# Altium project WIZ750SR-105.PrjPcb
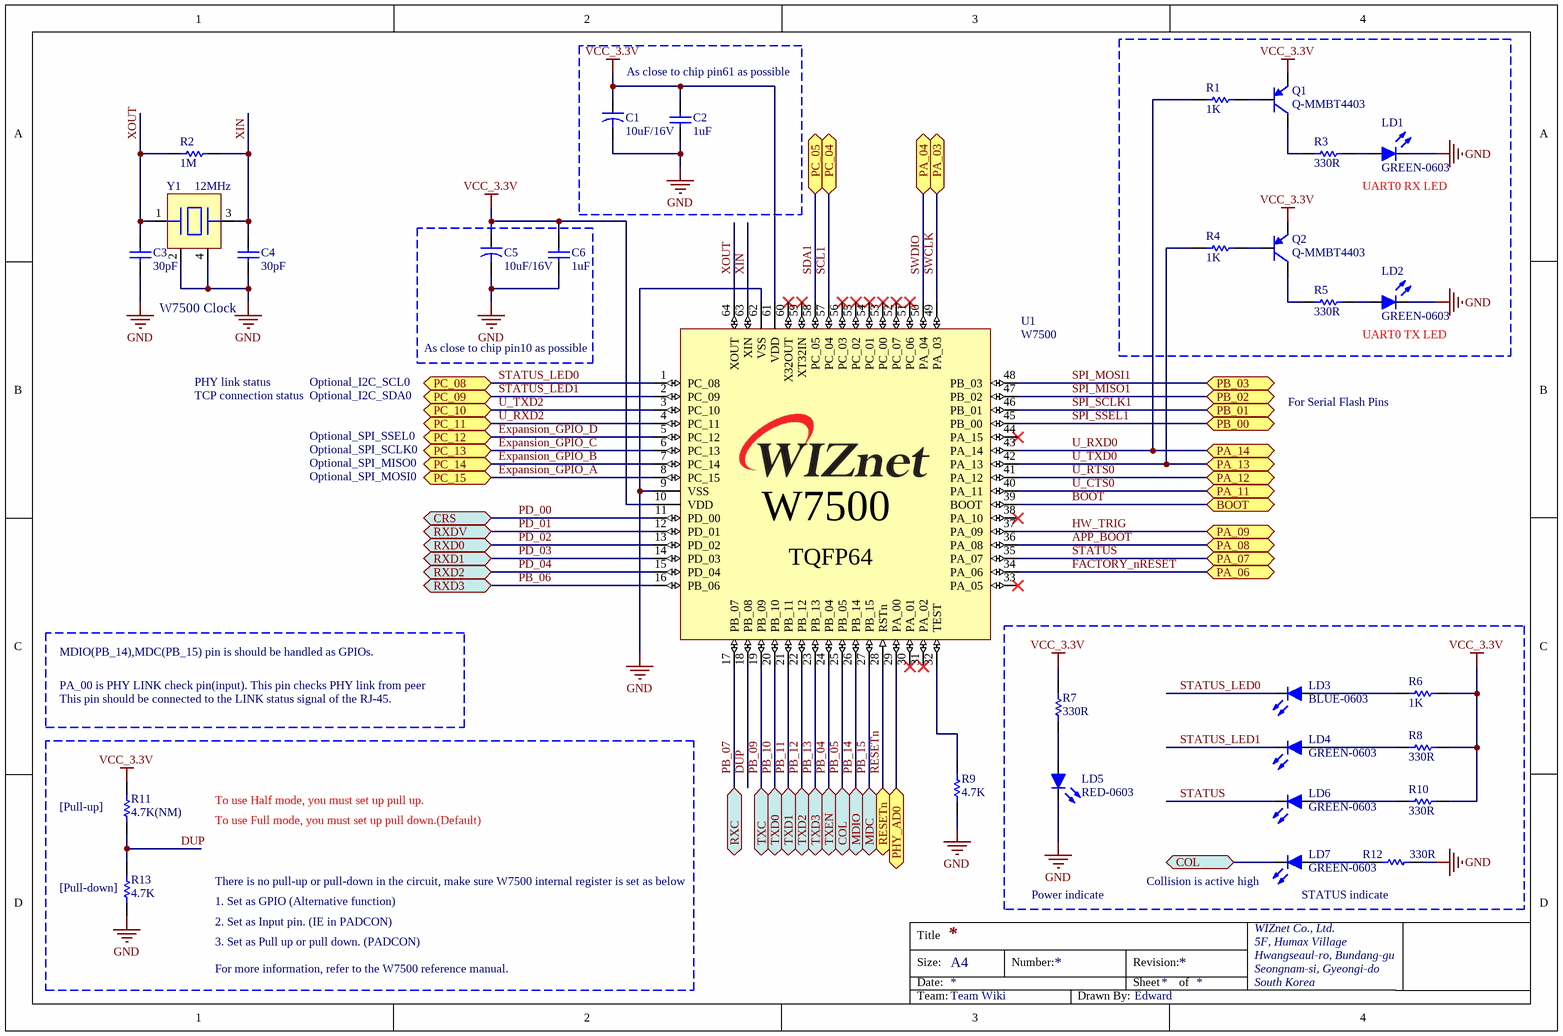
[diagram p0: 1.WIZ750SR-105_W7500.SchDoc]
4 sheets, 82 parts. Net scope: flat (ports and power ports of the same name join across sheets).
Board file: WIZ750SR-105.PcbDoc
Sheets:
  1.WIZ750SR-105_W7500.SchDoc
  2.WIZ750SR-105_IP101GRI.SchDoc
  3.WIZ750SR-105_OPTIONAL.SchDoc
  4.WIZ750SR-105_PINOUT.SchDoc

## Sheet 1.WIZ750SR-105_W7500.SchDoc
size A4; Team: Wiki

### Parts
C1  10uF/16V  [CAP-A Size]
C2  1uF  [CAP-0603]
C3  30pF  [CAP-0603]
C4  30pF  [CAP-0603]
C5  10uF/16V  [CAP-A Size]
C6  1uF  [CAP-0603]
LD1  GREEN-0603  [LED-0603-GREEN]
LD2  GREEN-0603  [LED-0603-GREEN]
LD3  BLUE-0603  [LED-0603-BLUE]
LD4  GREEN-0603  [LED-0603-GREEN]
LD5  RED-0603  [LED-0603-RED]
LD6  GREEN-0603  [LED-0603-GREEN]
LD7  GREEN-0603  [LED-0603-GREEN]
Q1  Q-MMBT4403  [SOT-23-3L]
Q2  Q-MMBT4403  [SOT-23-3L]
R1  1K  [RES-0603]
R2  1M  [RES-0603]
R3  330R  [RES-0603]
R4  1K  [RES-0603]
R5  330R  [RES-0603]
R6  1K  [RES-0603]
R7  330R  [RES-0603]
R8  330R  [RES-0603]
R9  4.7K  [RES-0603]
R10  330R  [RES-0603]
R11  4.7K(NM)  [RES-0603]
R12  330R  [RES-0603]
R13  4.7K  [RES-0603]
U1  W7500  [W7500-LQFP64]
Y1  12MHz  [OSC-TZ1067B]

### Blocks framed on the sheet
As close to chip pin61 as possible: C1 C2
As close to chip pin10 as possible: C5 C6

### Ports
BOOT, COL, CRS, MDC, MDIO, PA_03, PA_04, PA_06, PA_07, PA_08, PA_09, PA_11, PA_12, PA_13, PA_14, PB_00, PB_01, PB_02, PB_03, PC_04, PC_05, PC_08, PC_09, PC_10, PC_11, PC_12, PC_13, PC_14, PC_15, PHY_AD0, RESETn, RXC, RXD0, RXD1, RXD2, RXD3, RXDV, TXC, TXD0, TXD1, TXD2, TXD3, TXEN

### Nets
GND: C1.2 C2.1 C3.1 C4.1 C5.2 C6.1 LD1.2(K) LD2.2(K) LD5.2(K) R9.1 R12.2 R13.1 U1.9(VSS) U1.62(VSS) Y1.2 Y1.4
VCC_3.3V: C1.1 C2.2 C5.1 C6.2 Q1.2(E) Q2.2(E) R6.2 R7.1 R8.2 R10.2 R11.2 U1.10(VDD) U1.61(VDD)
APP_BOOT: U1.36(PA_08) ; port PA_08
BOOT: U1.39(BOOT) ; port BOOT
DUP: R11.1 R13.2 U1.18(PB_08)
Expansion_GPIO_A: U1.8(PC_15) ; port PC_15
Expansion_GPIO_B: U1.7(PC_14) ; port PC_14
Expansion_GPIO_C: U1.6(PC_13) ; port PC_13
Expansion_GPIO_D: U1.5(PC_12) ; port PC_12
FACTORY_nRESET: U1.34(PA_06) ; port PA_06
HW_TRIG: U1.37(PA_09) ; port PA_09
PB_04: U1.24(PB_04) ; port TXEN
PB_05: LD7.2(K) U1.25(PB_05) ; port COL
PB_06: U1.16(PB_06) ; port RXD3
PB_07: U1.17(PB_07) ; port RXC
PB_09: U1.19(PB_09) ; port TXC
PB_10: U1.20(PB_10) ; port TXD0
PB_11: U1.21(PB_11) ; port TXD1
PB_12: U1.22(PB_12) ; port TXD2
PB_13: U1.23(PB_13) ; port TXD3
PB_14: U1.26(PB_14) ; port MDIO
PB_15: U1.27(PB_15) ; port MDC
PD_00: U1.11(PD_00) ; port CRS
PD_01: U1.12(PD_01) ; port RXDV
PD_02: U1.13(PD_02) ; port RXD0
PD_03: U1.14(PD_03) ; port RXD1
PD_04: U1.15(PD_04) ; port RXD2
PHY_AD0: U1.29(PA_00) ; port PHY_AD0
RESETn: U1.28(RSTn) ; port RESETn
SCL1: U1.57(PC_04) ; port PC_04
SDA1: U1.58(PC_05) ; port PC_05
SPI_MISO1: U1.47(PB_02) ; port PB_02
SPI_MOSI1: U1.48(PB_03) ; port PB_03
SPI_SCLK1: U1.46(PB_01) ; port PB_01
SPI_SSEL1: U1.45(PB_00) ; port PB_00
STATUS: LD6.2(K) U1.35(PA_07) ; port PA_07
STATUS_LED0: LD3.2(K) U1.1(PC_08) ; port PC_08
STATUS_LED1: LD4.2(K) U1.2(PC_09) ; port PC_09
SWCLK: U1.49(PA_03) ; port PA_03
SWDIO: U1.50(PA_04) ; port PA_04
U_CTS0: U1.40(PA_11) ; port PA_11
U_RTS0: U1.41(PA_12) ; port PA_12
U_RXD0: R1.2 U1.43(PA_14) ; port PA_14
U_RXD2: U1.4(PC_11) ; port PC_11
U_TXD0: R4.2 U1.42(PA_13) ; port PA_13
U_TXD2: U1.3(PC_10) ; port PC_10
XIN: C4.2 R2.2 U1.63(XIN) Y1.3
XOUT: C3.2 R2.1 U1.64(XOUT) Y1.1
NetLD1_1: LD1.1(A) R3.1
NetLD2_1: LD2.1(A) R5.2
NetLD3_1: LD3.1(A) R6.1
NetLD4_1: LD4.1(A) R8.1
NetLD5_1: LD5.1(A) R7.2
NetLD6_1: LD6.1(A) R10.1
NetLD7_1: LD7.1(A) R12.1
NetQ1_1: Q1.1(B) R1.1
NetQ1_3: Q1.3(C) R3.2
NetQ2_1: Q2.1(B) R4.1
NetQ2_3: Q2.3(C) R5.1
NetR9_2: R9.2 U1.32(TEST)

Not connected (* = marked no-connect by the designer): U1 30(PA_01)* 31(PA_02)* 33(PA_05)* 38(PA_10)* 44(PA_15)* 51(PC_06)* 52(PC_07)* 53(PC_00)* 54(PC_01)* 55(PC_02)* 56(PC_03)* 59(XT32IN)* 60(X32OUT)*

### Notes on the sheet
- UART0 RX LED
- W7500 Clock
- PHY link status
- Optional_I2C_SCL0
- UART0 TX LED
- TCP connection status
- Optional_I2C_SDA0
- Optional_SPI_SSEL0
- For Serial Flash Pins
- Optional_SPI_SCLK0
- Optional_SPI_MISO0
- Optional_SPI_MOSI0
- MDIO(PB_14),MDC(PB_15) pin is should be handled as GPIOs.
- PA_00 is PHY LINK check pin(input). This pin checks PHY link from peer
- This pin should be connected to the LINK status signal of the RJ-45.
- (near R11) [Pull-up]
- To use Half mode, you must set up pull up.
- To use Full mode, you must set up pull down.(Default)
- (near R13) [Pull-down]
- There is no pull-up or pull-down in the circuit, make sure W7500 internal register is set as below
- 1. Set as GPIO (Alternative function)
- 2. Set as Input pin. (IE in PADCON)
- Power indicate
- (near LD7) Collision is active high
- STATUS indicate
- 3. Set as Pull up or pull down. (PADCON)
- For more information, refer to the W7500 reference manual.

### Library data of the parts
C1 C5 = CAP-A Size: Tantla CAP A Size EIA/IECQ 3216
C2-C4 C6 = CAP-0603: Ceramic CAP 0603(1608)
LD1-LD7 = LED-0603
Q1 Q2 = Q-MMBT4403: PNP General-Purpose Amplifier
R1-R13 = RES-0603
U1 = W7500: WIZnet ARM Cortex-M0
Y1 = OSC-TZ1067B-12MHz: X-tal 12MHz,3.2x2.5 SMD, CL=20pF

## Sheet 2.WIZ750SR-105_IP101GRI.SchDoc
size A4; Team: Wiki
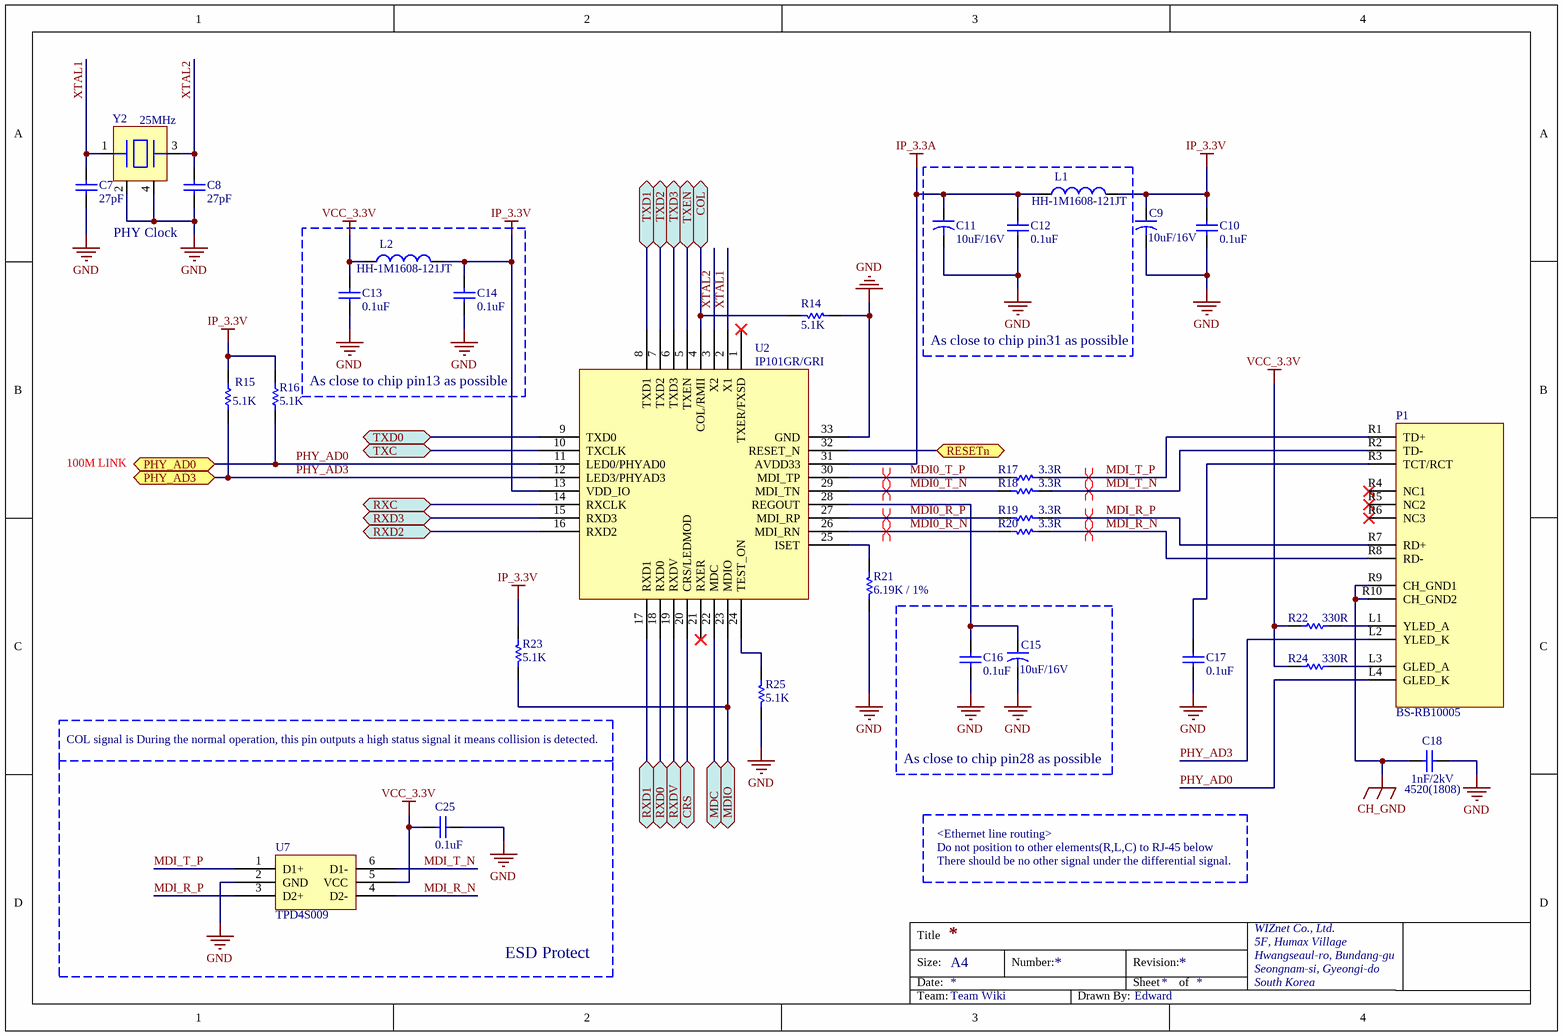
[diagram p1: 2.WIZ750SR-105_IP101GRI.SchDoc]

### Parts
C7  27pF  [CAP-0603]
C8  27pF  [CAP-0603]
C9  10uF/16V  [CAP-A Size]
C10  0.1uF  [CAP-0603]
C11  10uF/16V  [CAP-A Size]
C12  0.1uF  [CAP-0603]
C13  0.1uF  [CAP-0603]
C14  0.1uF  [CAP-0603]
C15  10uF/16V  [CAP-A Size]
C16  0.1uF  [CAP-0603]
C17  0.1uF  [CAP-0603]
C18  1nF/2kV  [CAP-1808]
C25  0.1uF  [CAP-0603]
L1  HH-1M1608-121JT  [IND-0603]
L2  HH-1M1608-121JT  [IND-0603]
P1  BS-RB10005  [RJ45-RB10005]
R14  5.1K  [RES-0603]
R15  5.1K  [RES-0603]
R16  5.1K  [RES-0603]
R17  3.3R  [RES-0603]
R18  3.3R  [RES-0603]
R19  3.3R  [RES-0603]
R20  3.3R  [RES-0603]
R21  6.19K / 1%  [RES-0603]
R22  330R  [RES-0603]
R23  5.1K  [RES-0603]
R24  330R  [RES-0603]
R25  5.1K  [RES-0603]
U2  IP101GR/GRI  [QFN32(0.4/4X4)]
U7  TPD4S009  [SOT-23-6L]
Y2  25MHz  [OSC-82J0626]

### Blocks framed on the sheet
As close to chip pin31 as possible: C11 C12 L1
As close to chip pin13 as possible: C13 C14 L2
As close to chip pin28 as possible: C15 C16

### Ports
COL, CRS, MDC, MDIO, PHY_AD0, PHY_AD3, RESETn, RXC, RXD0, RXD1, RXD2, RXD3, RXDV, TXC, TXD0, TXD1, TXD2, TXD3, TXEN

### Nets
CH_GND: C18.2 P1.R9(CH_GND1) P1.R10(CH_GND2)
GND: C7.1 C8.1 C9.2 C10.1 C11.2 C12.1 C13.1 C14.2 C15.2 C16.1 C17.1 C18.1 C25.2 R14.1 R21.1 R25.1 U2.33(GND) U7.2(GND) Y2.2 Y2.4
IP_3.3A: C11.1 C12.2 L1.1 U2.31(AVDD33)
IP_3.3V: C9.1 C10.2 C14.1 L1.2 L2.2 R15.1 R16.1 R23.2 U2.13(VDD_IO)
VCC_3.3V: C13.2 C25.1 L2.1 R22.1 R24.1 U7.5(VCC)
MDI0_R_N: R20.2 U2.26(MDI_RN)
MDI0_R_P: R19.2 U2.27(MDI_RP)
MDI0_T_N: R18.2 U2.29(MDI_TN)
MDI0_T_P: R17.2 U2.30(MDI_TP)
MDI_R_N: P1.R8(RD-) R20.1 U7.4(D2-)
MDI_R_P: P1.R7(RD+) R19.1 U7.3(D2+)
MDI_T_N: P1.R2(TD-) R18.1 U7.6(D1-)
MDI_T_P: P1.R1(TD+) R17.1 U7.1(D1+)
PB_04: U2.5(TXEN) ; port TXEN
PB_05: R14.2 U2.4(COL/RMII) ; port COL
PB_06: U2.15(RXD3) ; port RXD3
PB_07: U2.14(RXCLK) ; port RXC
PB_09: U2.10(TXCLK) ; port TXC
PB_10: U2.9(TXD0) ; port TXD0
PB_11: U2.8(TXD1) ; port TXD1
PB_12: U2.7(TXD2) ; port TXD2
PB_13: U2.6(TXD3) ; port TXD3
PB_14: R23.1 U2.23(MDIO) ; port MDIO
PB_15: U2.22(MDC) ; port MDC
PD_00: U2.20(CRS/LEDMOD) ; port CRS
PD_01: U2.19(RXDV) ; port RXDV
PD_02: U2.18(RXD0) ; port RXD0
PD_03: U2.17(RXD1) ; port RXD1
PD_04: U2.16(RXD2) ; port RXD2
PHY_AD0: P1.L4(GLED_K) R16.2 U2.11(LED0/PHYAD0) ; port PHY_AD0
PHY_AD3: P1.L2(YLED_K) R15.2 U2.12(LED3/PHYAD3) ; port PHY_AD3
RESETn: U2.32(RESET_N) ; port RESETn
XTAL1: C7.2 U2.2(X1) Y2.1
XTAL2: C8.2 U2.3(X2) Y2.3
NetC15_1: C15.1 C16.2 U2.28(REGOUT)
NetC17_2: C17.2 P1.R3(TCT/RCT)
NetP1_L1: P1.L1(YLED_A) R22.2
NetP1_L3: P1.L3(GLED_A) R24.2
NetR21_2: R21.2 U2.25(ISET)
NetR25_2: R25.2 U2.24(TEST_ON)

Not connected (* = marked no-connect by the designer): P1 R4(NC1)* R5(NC2)* R6(NC3)*; U2 1(TXER/FXSD)* 21(RXER)*

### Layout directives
differential pair: MDI0_R_N, MDI0_R_P, MDI0_T_N, MDI0_T_P, MDI_R_N, MDI_R_P, MDI_T_N, MDI_T_P

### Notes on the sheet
- PHY Clock
- 100M LINK
- (near R25) COL signal is During the normal operation, this pin outputs a high status signal it means collision is detected.
- <Ethernet line routing>
- Do not position to other elements(R,L,C) to RJ-45 below
- (near C18) 4520(1808)
- There should be no other signal under the differential signal.
- ESD Protect

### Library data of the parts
C7 C8 C10 C13 C14 C16 C17 C25 = CAP-0603: Ceramic CAP 0603(1608)
C9 C11 C15 = CAP-A Size: Tantla CAP A Size EIA/IECQ 3216
C12 = CAP-0402: Ceramic CAP 0402(1005)
C18 = CAP-1808: Ceramic CAP 1808(4520)
L1 L2 = IND-0603: Inductor 0603(1608)
P1 = RB1-125BAG1A: 10/100 BASE-TX MAGJACK
R14-R25 = RES-0603
U2 = IP101GR/GRI: Pakage: VQFN-32
U7 = tpd4s009: 6-PIN SOT DBVor DCK Package
Y2 = OSC-82J0626-25MHz: X-tal 25MHz,3.2x2.5 SMD, CL=18pF

## Sheet 3.WIZ750SR-105_OPTIONAL.SchDoc
size A4; Team: Wiki
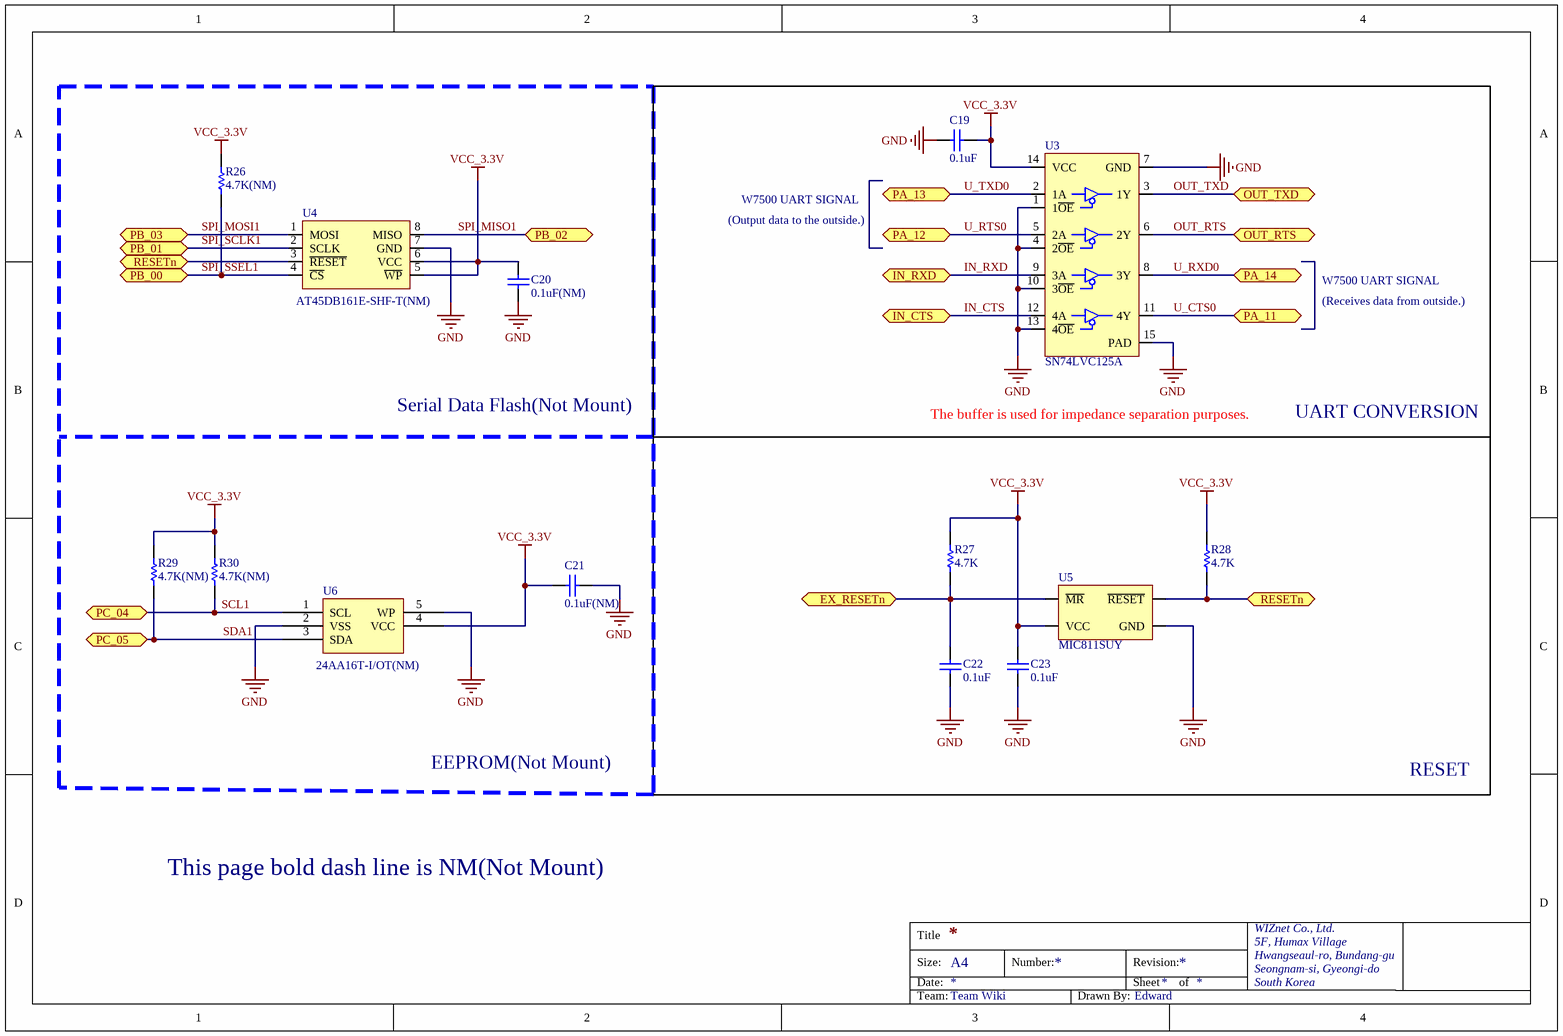
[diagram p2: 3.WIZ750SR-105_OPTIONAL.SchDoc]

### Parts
C19  0.1uF  [CAP-0603]
C20  0.1uF(NM)  [CAP-0603]
C21  0.1uF(NM)  [CAP-0603]
C22  0.1uF  [CAP-0603]
C23  0.1uF  [CAP-0603]
R26  4.7K(NM)  [RES-0603]
R27  4.7K  [RES-0603]
R28  4.7K  [RES-0603]
R29  4.7K(NM)  [RES-0603]
R30  4.7K(NM)  [RES-0603]
U3  SN74LVC125A  [VQFN14(0.5/3.65X3.65)]
U4  AT45DB161E-SHF-T(NM)  [SO-08-EIAJ]
U5  MIC811SUY  [SOT-143]
U6  24AA16T-I/OT(NM)  [SOT-23-5L]

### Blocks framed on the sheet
UART CONVERSION: C19 U3

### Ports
EX_RESETn, IN_CTS, IN_RXD, OUT_RTS, OUT_TXD, PA_11, PA_12, PA_13, PA_14, PB_00, PB_01, PB_02, PB_03, PC_04, PC_05, RESETn

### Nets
GND: C19.2 C20.2 C21.1 C22.1 C23.1 U3.1(1~{OE}) U3.4(2~{OE}) U3.7(GND) U3.10(3~{OE}) U3.13(4~{OE}) U3.15(PAD) U4.7(GND) U5.1(GND) U6.2(VSS) U6.5(WP)
VCC_3.3V: C19.1 C20.1 C21.2 C23.2 R26.2 R27.2 R28.2 R29.2 R30.2 U3.14(VCC) U4.5(~{WP}) U4.6(VCC) U5.4(VCC) U6.4(VCC)
EX_RESETn: C22.2 R27.1 U5.3(~{MR}) ; port EX_RESETn
IN_CTS: U3.12(4A) ; port IN_CTS
IN_RXD: U3.9(3A) ; port IN_RXD
OUT_RTS: U3.6(2Y) ; port OUT_RTS
OUT_TXD: U3.3(1Y) ; port OUT_TXD
RESETn: R28.1 U4.3(~{RESET}) U5.2(~{RESET}) ; port RESETn
SCL1: R30.1 U6.1(SCL) ; port PC_04
SDA1: R29.1 U6.3(SDA) ; port PC_05
SPI_MISO1: U4.8(MISO) ; port PB_02
SPI_MOSI1: U4.1(MOSI) ; port PB_03
SPI_SCLK1: U4.2(SCLK) ; port PB_01
SPI_SSEL1: R26.1 U4.4(~{CS}) ; port PB_00
U_CTS0: U3.11(4Y) ; port PA_11
U_RTS0: U3.5(2A) ; port PA_12
U_RXD0: U3.8(3Y) ; port PA_14
U_TXD0: U3.2(1A) ; port PA_13

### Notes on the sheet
- (Output data to the outside.)
- W7500 UART SIGNAL
- (Receives data from outside.)
- Serial Data Flash(Not Mount)
- The buffer is used for impedance separation purposes.
- EEPROM(Not Mount)
- RESET
- This page bold dash line is NM(Not Mount)

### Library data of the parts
C19-C23 = CAP-0603: Ceramic CAP 0603(1608)
R26-R30 = RES-0603
U3 = SN74LVC125A: Quadruple Bus Buffer Gate With 3-State Outputs
U4 = AT45DB161E-SHF-T: 16-Mbit DataFlash, 2.3V or 2.5V Minimum SPI Serial Flash Memory
U5 = MIC811SUY: Microprocessor Reset Circuits
U6 = 24AAxxT-i-OT: SOT-23

## Sheet 4.WIZ750SR-105_PINOUT.SchDoc
size A4; Team: Wiki
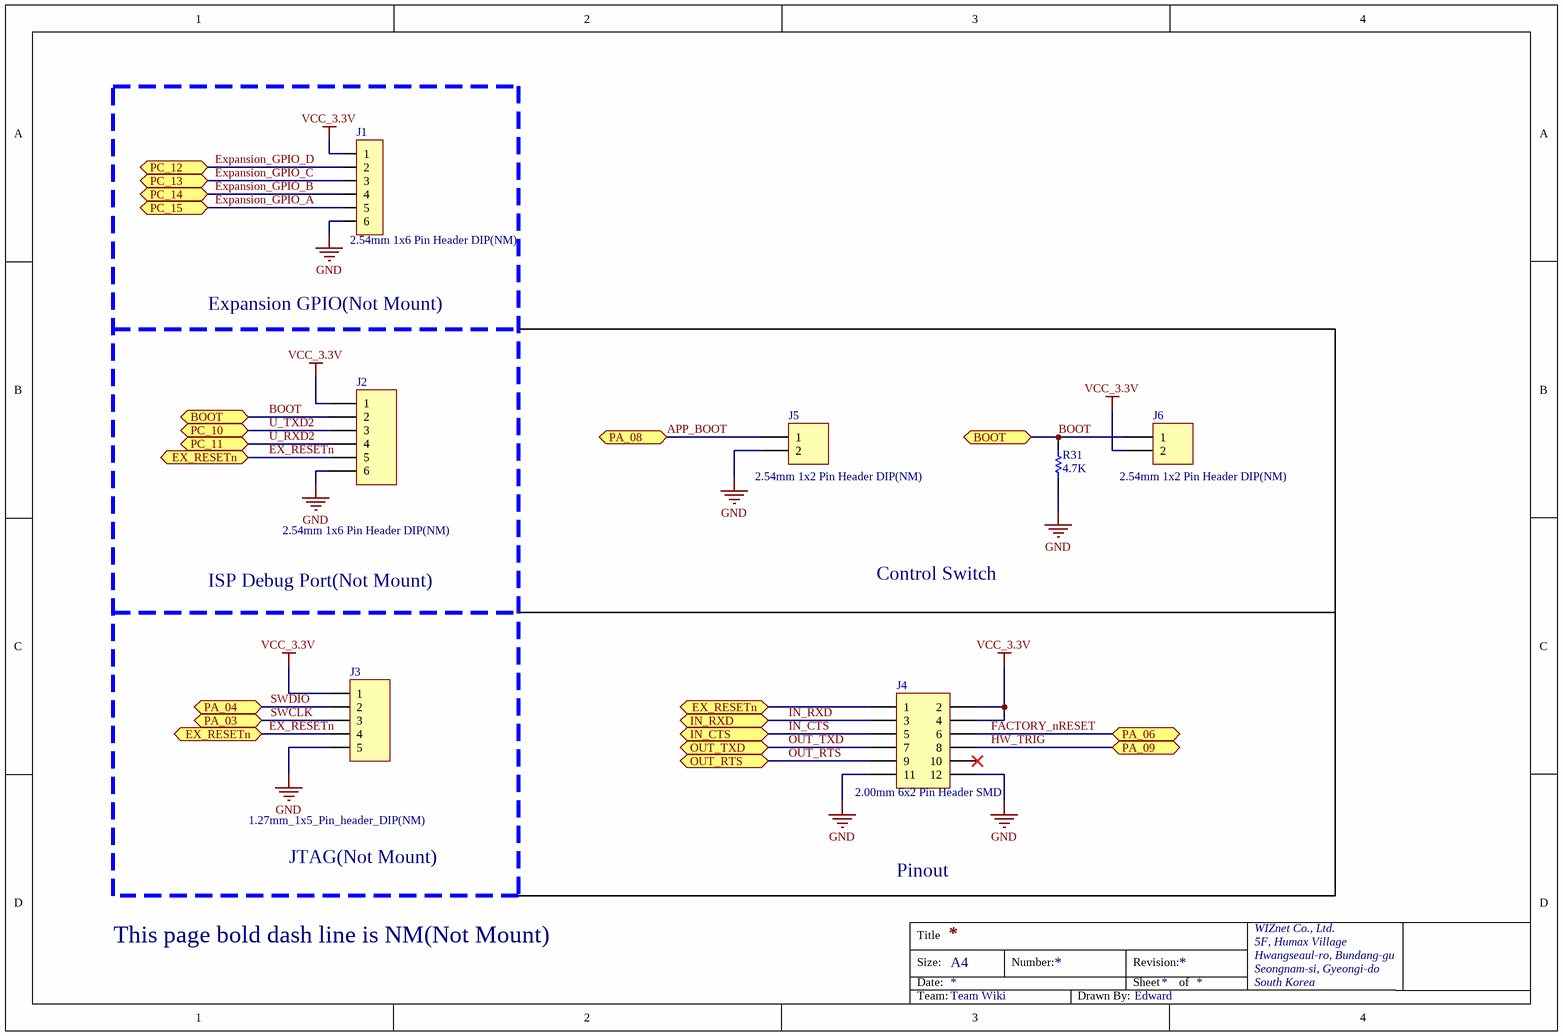
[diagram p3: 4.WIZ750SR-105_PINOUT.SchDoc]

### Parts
J1  2.54mm 1x6 Pin Header DIP(NM)  [IDC-1X6]
J2  2.54mm 1x6 Pin Header DIP(NM)  [IDC-1X6]
J3  1.27mm_1x5_Pin_header_DIP(NM)  [IDC-1X5(1.27MM)]
J4  2.00mm 6x2 Pin Header SMD  [MOLEX-SD-87759-12]
J5  2.54mm 1x2 Pin Header DIP(NM)  [IDC-1X2]
J6  2.54mm 1x2 Pin Header DIP(NM)  [IDC-1X2]
R31  4.7K  [RES-0603]

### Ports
BOOT, EX_RESETn, IN_CTS, IN_RXD, OUT_RTS, OUT_TXD, PA_03, PA_04, PA_06, PA_08, PA_09, PC_10, PC_11, PC_12, PC_13, PC_14, PC_15

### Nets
GND: J1.6 J2.6 J3.5 J4.11 J4.12 J5.2 R31.2
VCC_3.3V: J1.1 J2.1 J3.1 J4.2 J4.4 J6.2
APP_BOOT: J5.1 ; port PA_08
BOOT: J2.2 J6.1 R31.1 ; port BOOT
EX_RESETn: J2.5 J3.4 J4.1 ; port EX_RESETn
Expansion_GPIO_A: J1.5 ; port PC_15
Expansion_GPIO_B: J1.4 ; port PC_14
Expansion_GPIO_C: J1.3 ; port PC_13
Expansion_GPIO_D: J1.2 ; port PC_12
FACTORY_nRESET: J4.6 ; port PA_06
HW_TRIG: J4.8 ; port PA_09
IN_CTS: J4.5 ; port IN_CTS
IN_RXD: J4.3 ; port IN_RXD
OUT_RTS: J4.9 ; port OUT_RTS
OUT_TXD: J4.7 ; port OUT_TXD
SWCLK: J3.3 ; port PA_03
SWDIO: J3.2 ; port PA_04
U_RXD2: J2.4 ; port PC_11
U_TXD2: J2.3 ; port PC_10

Not connected (* = marked no-connect by the designer): J4 10*

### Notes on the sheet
- Expansion GPIO(Not Mount)
- Control Switch
- ISP Debug Port(Not Mount)
- JTAG(Not Mount)
- Pinout
- This page bold dash line is NM(Not Mount)

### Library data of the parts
J1 = 2.54mm 1x6 Pin Header DIP
J2 = Header 6: Header, 6-Pin
J3 = 1.27mm_1x5_Pin_header_DIP
J4 = Header 6X2: Header, 6-Pin, Dual row
J5 J6 = Header 1x2: pin header 2.54mm 1x2
R31 = RES-0603

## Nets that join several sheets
GND: 1.WIZ750SR-105_W7500 (16 pins), 2.WIZ750SR-105_IP101GRI (20 pins), 3.WIZ750SR-105_OPTIONAL (15 pins), 4.WIZ750SR-105_PINOUT (7 pins)
VCC_3.3V: 1.WIZ750SR-105_W7500 (13 pins), 2.WIZ750SR-105_IP101GRI (6 pins), 3.WIZ750SR-105_OPTIONAL (14 pins), 4.WIZ750SR-105_PINOUT (6 pins)
APP_BOOT: 1.WIZ750SR-105_W7500 (U1.36), 4.WIZ750SR-105_PINOUT (J5.1)
BOOT: 1.WIZ750SR-105_W7500 (U1.39), 4.WIZ750SR-105_PINOUT (J2.2 J6.1 R31.1)
EX_RESETn: 3.WIZ750SR-105_OPTIONAL (C22.2 R27.1 U5.3), 4.WIZ750SR-105_PINOUT (J2.5 J3.4 J4.1)
Expansion_GPIO_A: 1.WIZ750SR-105_W7500 (U1.8), 4.WIZ750SR-105_PINOUT (J1.5)
Expansion_GPIO_B: 1.WIZ750SR-105_W7500 (U1.7), 4.WIZ750SR-105_PINOUT (J1.4)
Expansion_GPIO_C: 1.WIZ750SR-105_W7500 (U1.6), 4.WIZ750SR-105_PINOUT (J1.3)
Expansion_GPIO_D: 1.WIZ750SR-105_W7500 (U1.5), 4.WIZ750SR-105_PINOUT (J1.2)
FACTORY_nRESET: 1.WIZ750SR-105_W7500 (U1.34), 4.WIZ750SR-105_PINOUT (J4.6)
HW_TRIG: 1.WIZ750SR-105_W7500 (U1.37), 4.WIZ750SR-105_PINOUT (J4.8)
IN_CTS: 3.WIZ750SR-105_OPTIONAL (U3.12), 4.WIZ750SR-105_PINOUT (J4.5)
IN_RXD: 3.WIZ750SR-105_OPTIONAL (U3.9), 4.WIZ750SR-105_PINOUT (J4.3)
OUT_RTS: 3.WIZ750SR-105_OPTIONAL (U3.6), 4.WIZ750SR-105_PINOUT (J4.9)
OUT_TXD: 3.WIZ750SR-105_OPTIONAL (U3.3), 4.WIZ750SR-105_PINOUT (J4.7)
PB_04: 1.WIZ750SR-105_W7500 (U1.24), 2.WIZ750SR-105_IP101GRI (U2.5)
PB_05: 1.WIZ750SR-105_W7500 (LD7.2 U1.25), 2.WIZ750SR-105_IP101GRI (R14.2 U2.4)
PB_06: 1.WIZ750SR-105_W7500 (U1.16), 2.WIZ750SR-105_IP101GRI (U2.15)
PB_07: 1.WIZ750SR-105_W7500 (U1.17), 2.WIZ750SR-105_IP101GRI (U2.14)
PB_09: 1.WIZ750SR-105_W7500 (U1.19), 2.WIZ750SR-105_IP101GRI (U2.10)
PB_10: 1.WIZ750SR-105_W7500 (U1.20), 2.WIZ750SR-105_IP101GRI (U2.9)
PB_11: 1.WIZ750SR-105_W7500 (U1.21), 2.WIZ750SR-105_IP101GRI (U2.8)
PB_12: 1.WIZ750SR-105_W7500 (U1.22), 2.WIZ750SR-105_IP101GRI (U2.7)
PB_13: 1.WIZ750SR-105_W7500 (U1.23), 2.WIZ750SR-105_IP101GRI (U2.6)
PB_14: 1.WIZ750SR-105_W7500 (U1.26), 2.WIZ750SR-105_IP101GRI (R23.1 U2.23)
PB_15: 1.WIZ750SR-105_W7500 (U1.27), 2.WIZ750SR-105_IP101GRI (U2.22)
PD_00: 1.WIZ750SR-105_W7500 (U1.11), 2.WIZ750SR-105_IP101GRI (U2.20)
PD_01: 1.WIZ750SR-105_W7500 (U1.12), 2.WIZ750SR-105_IP101GRI (U2.19)
PD_02: 1.WIZ750SR-105_W7500 (U1.13), 2.WIZ750SR-105_IP101GRI (U2.18)
PD_03: 1.WIZ750SR-105_W7500 (U1.14), 2.WIZ750SR-105_IP101GRI (U2.17)
PD_04: 1.WIZ750SR-105_W7500 (U1.15), 2.WIZ750SR-105_IP101GRI (U2.16)
PHY_AD0: 1.WIZ750SR-105_W7500 (U1.29), 2.WIZ750SR-105_IP101GRI (P1.L4 R16.2 U2.11)
RESETn: 1.WIZ750SR-105_W7500 (U1.28), 2.WIZ750SR-105_IP101GRI (U2.32), 3.WIZ750SR-105_OPTIONAL (R28.1 U4.3 U5.2)
SCL1: 1.WIZ750SR-105_W7500 (U1.57), 3.WIZ750SR-105_OPTIONAL (R30.1 U6.1)
SDA1: 1.WIZ750SR-105_W7500 (U1.58), 3.WIZ750SR-105_OPTIONAL (R29.1 U6.3)
SPI_MISO1: 1.WIZ750SR-105_W7500 (U1.47), 3.WIZ750SR-105_OPTIONAL (U4.8)
SPI_MOSI1: 1.WIZ750SR-105_W7500 (U1.48), 3.WIZ750SR-105_OPTIONAL (U4.1)
SPI_SCLK1: 1.WIZ750SR-105_W7500 (U1.46), 3.WIZ750SR-105_OPTIONAL (U4.2)
SPI_SSEL1: 1.WIZ750SR-105_W7500 (U1.45), 3.WIZ750SR-105_OPTIONAL (R26.1 U4.4)
SWCLK: 1.WIZ750SR-105_W7500 (U1.49), 4.WIZ750SR-105_PINOUT (J3.3)
SWDIO: 1.WIZ750SR-105_W7500 (U1.50), 4.WIZ750SR-105_PINOUT (J3.2)
U_CTS0: 1.WIZ750SR-105_W7500 (U1.40), 3.WIZ750SR-105_OPTIONAL (U3.11)
U_RTS0: 1.WIZ750SR-105_W7500 (U1.41), 3.WIZ750SR-105_OPTIONAL (U3.5)
U_RXD0: 1.WIZ750SR-105_W7500 (R1.2 U1.43), 3.WIZ750SR-105_OPTIONAL (U3.8)
U_RXD2: 1.WIZ750SR-105_W7500 (U1.4), 4.WIZ750SR-105_PINOUT (J2.4)
U_TXD0: 1.WIZ750SR-105_W7500 (R4.2 U1.42), 3.WIZ750SR-105_OPTIONAL (U3.2)
U_TXD2: 1.WIZ750SR-105_W7500 (U1.3), 4.WIZ750SR-105_PINOUT (J2.3)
